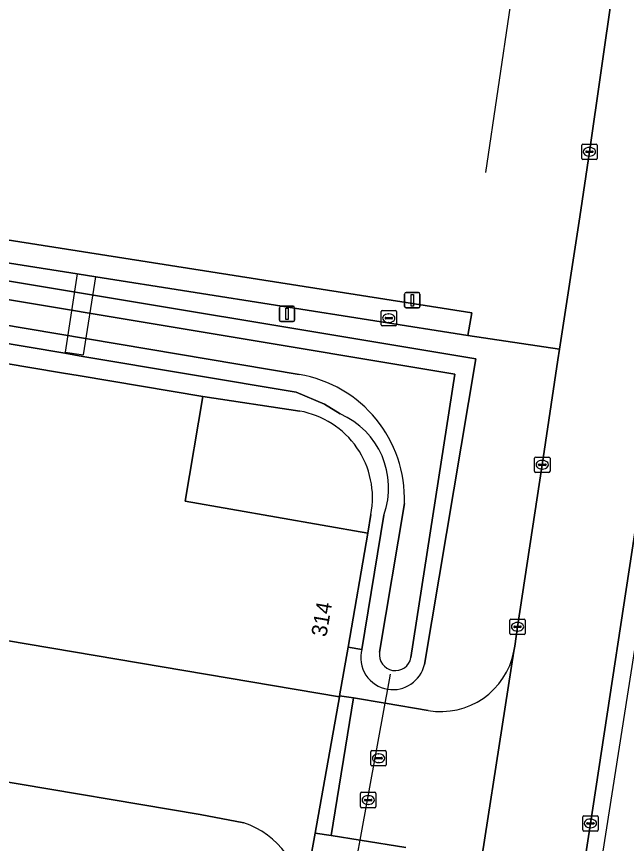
# Model space of a CAD drawing. Extents: x 161090 to 161692, y 379509 to 380907.
# Drawn here: x 161499.4 to 161538.9, y 379916 to 379969.5 of the extents above; entities that cross this region are included whole.
import ezdxf

# ---------------------------------------------------------------- set-up
doc = ezdxf.new("R2010")
doc.units = 0
for name, color, linetype in [('IMGEO_Berm_groen', 7, 'Continuous'), ('IMGEO_Dek', 7, 'Continuous'), ('IMGEO_Duiker', 7, 'Continuous'), ('IMGEO_Erf', 7, 'Continuous'), ('IMGEO_Groenvoorziening', 7, 'Continuous'), ('IMGEO_Hek', 7, 'Continuous'), ('IMGEO_Kolk', 7, 'Continuous'), ('IMGEO_Lichtmast', 7, 'Continuous'), ('IMGEO_Oever', 7, 'Continuous'), ('IMGEO_OVBaan_gesloten', 7, 'Continuous'), ('IMGEO_Pand', 7, 'Continuous'), ('IMGEO_Pand_nummerreeks', 7, 'Continuous'), ('IMGEO_Rijbaan_lokaal_open', 7, 'Continuous'), ('IMGEO_Rioolput', 7, 'Continuous'), ('IMGEO_Voetpad_gesloten', 7, 'Continuous'), ('IMGEO_Voetpad_open', 7, 'Continuous'), ('IMGEO_Waterleidingput', 7, 'Continuous'), ('IMGEO_Waterloop', 7, 'Continuous')]:
    doc.layers.add(name, color=color, linetype=linetype)

msp = doc.modelspace()

# ---------------------------------------------------------------- linework, layer by layer
at = {"layer": 'IMGEO_Berm_groen'}
msp.add_lwpolyline([(161568.964, 380134.54), (161565.202, 380110.378), (161562.114, 380090.616), (161558.714, 380068.427), (161555.445, 380047.213), (161553.622, 380035.058), (161552.155, 380025.015), (161549.143, 380002.747), (161547.501, 379990.953), (161546.186, 379981.488), (161544.637, 379970.686), (161543.025, 379959.699), (161541.406, 379948.743), (161539.958, 379939.476), (161536.563, 379917.273), (161533.152, 379895.072), (161532.543, 379891.174), (161536.797, 379890.693), (161538.081, 379899.575), (161547.32, 379960.011), (161564.94, 380073.828), (161570.943, 380112.605), (161573.298, 380127.137)], dxfattribs=at)
at = {"layer": 'IMGEO_Dek'}
msp.add_lwpolyline([(161503.353, 379952.839), (161502.581, 379947.775), (161503.765, 379947.6), (161504.564, 379952.647)], close=True, dxfattribs=at)
at = {"layer": 'IMGEO_Duiker'}
msp.add_lwpolyline([(161521.213, 379913.764), (161521.359, 379914.557), (161521.659, 379916.19), (161523.289, 379925.051), (161523.456, 379925.959), (161523.636, 379926.94)], dxfattribs=at)
at = {"layer": 'IMGEO_Erf'}
for points in [[(161511.482, 379944.901), (161510.34, 379938.122), (161522.174, 379936.061), (161522.363, 379937.271)], [(161517.757, 379943.954), (161511.482, 379944.901)]]:
    msp.add_lwpolyline(points, dxfattribs=at)
msp.add_arc((161516.777, 379938.35), 5.689, 349.0692, 80.0809, dxfattribs=at)
at = {"layer": 'IMGEO_Groenvoorziening'}
for points in [[(161468.78, 380015.282), (161460.249, 379961.111), (161528.895, 379950.307), (161528.642, 379948.839), (161534.566, 379947.954), (161535.873, 379956.523), (161536.498, 379960.739), (161537.983, 379971.128)], [(161531.614, 379928.422), (161531.665, 379928.747), (161531.848, 379929.997), (161533.448, 379940.484), (161534.462, 379947.272), (161534.566, 379947.954), (161528.642, 379948.839), (161504.564, 379952.647), (161503.353, 379952.839), (161490.618, 379954.853), (161489.414, 379955.043), (161461.018, 379959.534)], [(161463.491, 379958.267), (161529.143, 379947.348), (161525.825, 379927.554)], [(161521.771, 379928.537), (161520.887, 379928.67), (161520.341, 379925.533), (161521.239, 379925.396), (161523.289, 379925.051), (161526.064, 379924.584)], [(161524.623, 379915.703), (161521.659, 379916.19), (161519.795, 379916.496), (161518.754, 379916.647), (161518.179, 379913.425), (161519.482, 379913.207)]]:
    msp.add_lwpolyline(points, dxfattribs=at)
for centre, radius, start, end in [((161523.791, 379928.018), 2.086, 165.5898, 260.7481), ((161526.889, 379929.322), 4.81, 260.1205, 349.2097), ((161523.788, 379928.023), 2.091, 260.8708, 347.0324)]:
    msp.add_arc(centre, radius, start, end, dxfattribs=at)
at = {"layer": 'IMGEO_Hek'}
for points in [[(161554.512, 380126.608), (161529.782, 379959.399)], [(161570.009, 380123.365), (161550.635, 380000), (161531.34, 379877.143), (161526.851, 379847.795)]]:
    msp.add_lwpolyline(points, dxfattribs=at)
at = {"layer": 'IMGEO_Kolk'}
for p, q in [((161535.997, 379960.313), (161535.997, 379961.165)), ((161536.072, 379961.239), (161536.924, 379961.239)), ((161536.485, 379961.019), (161536.51, 379961.019)), ((161536.998, 379961.165), (161536.998, 379960.313)), ((161536.256, 379960.733), (161536.256, 379960.745)), ((161536.694, 379960.696), (161536.296, 379960.696)), ((161536.299, 379960.782), (161536.697, 379960.782)), ((161536.508, 379960.459), (161536.483, 379960.459)), ((161536.74, 379960.745), (161536.74, 379960.733)), ((161536.924, 379960.239), (161536.072, 379960.239)), ((161532.947, 379940.058), (161532.947, 379940.91)), ((161533.022, 379940.984), (161533.874, 379940.984)), ((161533.435, 379940.764), (161533.46, 379940.764)), ((161533.948, 379940.91), (161533.948, 379940.058)), ((161533.206, 379940.478), (161533.206, 379940.49)), ((161533.644, 379940.441), (161533.246, 379940.441)), ((161533.249, 379940.527), (161533.647, 379940.527)), ((161533.458, 379940.204), (161533.433, 379940.204)), ((161533.69, 379940.49), (161533.69, 379940.478)), ((161533.874, 379939.984), (161533.022, 379939.984)), ((161531.347, 379929.571), (161531.347, 379930.423)), ((161531.422, 379930.497), (161532.274, 379930.497)), ((161532.348, 379930.423), (161532.348, 379929.571)), ((161531.606, 379929.991), (161531.606, 379930.003)), ((161532.044, 379929.954), (161531.646, 379929.954)), ((161531.649, 379930.04), (161532.047, 379930.04)), ((161531.835, 379930.277), (161531.86, 379930.277)), ((161532.09, 379930.003), (161532.09, 379929.991)), ((161532.274, 379929.497), (161531.422, 379929.497)), ((161531.858, 379929.717), (161531.833, 379929.717)), ((161536.062, 379916.847), (161536.062, 379917.699)), ((161536.137, 379917.773), (161536.989, 379917.773)), ((161536.55, 379917.553), (161536.575, 379917.553)), ((161537.063, 379917.699), (161537.063, 379916.847)), ((161536.321, 379917.267), (161536.321, 379917.279)), ((161536.759, 379917.23), (161536.361, 379917.23)), ((161536.364, 379917.316), (161536.762, 379917.316)), ((161536.573, 379916.993), (161536.548, 379916.993)), ((161536.805, 379917.279), (161536.805, 379917.267)), ((161536.989, 379916.773), (161536.137, 379916.773))]:
    msp.add_line(p, q, dxfattribs=at)
for points in [[(161535.997, 379960.313), (161535.997, 379961.165)], [(161536.072, 379961.239), (161536.924, 379961.239)], [(161536.998, 379961.165), (161536.998, 379960.313)], [(161536.924, 379960.239), (161536.072, 379960.239)], [(161532.947, 379940.058), (161532.947, 379940.91)], [(161533.022, 379940.984), (161533.874, 379940.984)], [(161533.948, 379940.91), (161533.948, 379940.058)], [(161533.874, 379939.984), (161533.022, 379939.984)], [(161531.347, 379929.571), (161531.347, 379930.423)], [(161531.422, 379930.497), (161532.274, 379930.497)], [(161532.348, 379930.423), (161532.348, 379929.571)], [(161532.274, 379929.497), (161531.422, 379929.497)], [(161536.062, 379916.847), (161536.062, 379917.699)], [(161536.137, 379917.773), (161536.989, 379917.773)], [(161537.063, 379917.699), (161537.063, 379916.847)], [(161536.989, 379916.773), (161536.137, 379916.773)]]:
    msp.add_lwpolyline(points, dxfattribs=at)
for centre, radius, start, end in [((161536.074, 379961.163), 0.0765, 91.552, 178.448), ((161536.074, 379961.163), 0.0765, 91.552, 178.448), ((161536.922, 379961.163), 0.0765, 1.552, 88.448), ((161536.922, 379961.163), 0.0765, 1.552, 88.448), ((161536.296, 379960.742), 0.0403, 85.8775, 175.7526), ((161536.293, 379960.732), 0.0366, 178.938, 274.7102), ((161536.697, 379960.739), 0.043, 264.8664, 352.4533), ((161536.701, 379960.744), 0.0386, 1.7309, 96.639), ((161536.074, 379960.315), 0.0765, 181.552, 268.448), ((161536.074, 379960.315), 0.0765, 181.552, 268.448), ((161536.922, 379960.315), 0.0765, 271.552, 358.448), ((161536.922, 379960.315), 0.0765, 271.552, 358.448), ((161533.024, 379940.908), 0.0765, 91.552, 178.448), ((161533.024, 379940.908), 0.0765, 91.552, 178.448), ((161533.872, 379940.908), 0.0765, 1.552, 88.448), ((161533.872, 379940.908), 0.0765, 1.552, 88.448), ((161533.024, 379940.06), 0.0765, 181.552, 268.448), ((161533.024, 379940.06), 0.0765, 181.552, 268.448), ((161533.246, 379940.487), 0.0403, 85.8775, 175.7526), ((161533.243, 379940.477), 0.0366, 178.938, 274.7102), ((161533.647, 379940.484), 0.043, 264.8664, 352.4533), ((161533.651, 379940.489), 0.0386, 1.7309, 96.639), ((161533.872, 379940.06), 0.0765, 271.552, 358.448), ((161533.872, 379940.06), 0.0765, 271.552, 358.448), ((161531.424, 379930.421), 0.0765, 91.552, 178.448), ((161531.424, 379930.421), 0.0765, 91.552, 178.448), ((161532.272, 379930.421), 0.0765, 1.552, 88.448), ((161532.272, 379930.421), 0.0765, 1.552, 88.448), ((161531.646, 379930), 0.0403, 85.8775, 175.7526), ((161531.643, 379929.99), 0.0366, 178.938, 274.7102), ((161532.047, 379929.997), 0.043, 264.8664, 352.4533), ((161532.051, 379930.002), 0.0386, 1.7309, 96.639), ((161531.424, 379929.573), 0.0765, 181.552, 268.448), ((161531.424, 379929.573), 0.0765, 181.552, 268.448), ((161532.272, 379929.573), 0.0765, 271.552, 358.448), ((161532.272, 379929.573), 0.0765, 271.552, 358.448), ((161536.139, 379917.697), 0.0765, 91.552, 178.448), ((161536.139, 379917.697), 0.0765, 91.552, 178.448), ((161536.987, 379917.697), 0.0765, 1.552, 88.448), ((161536.987, 379917.697), 0.0765, 1.552, 88.448), ((161536.361, 379917.276), 0.0403, 85.8775, 175.7526), ((161536.358, 379917.266), 0.0366, 178.938, 274.7102), ((161536.762, 379917.273), 0.043, 264.8664, 352.4533), ((161536.766, 379917.278), 0.0386, 1.7309, 96.639), ((161536.139, 379916.849), 0.0765, 181.552, 268.448), ((161536.139, 379916.849), 0.0765, 181.552, 268.448), ((161536.987, 379916.849), 0.0765, 271.552, 358.448), ((161536.987, 379916.849), 0.0765, 271.552, 358.448)]:
    msp.add_arc(centre, radius, start, end, dxfattribs=at)
for centre, major_axis, ratio, start_param, end_param in [((161536.484, 379960.739), (-0.387, 0.002), 0.722429, 4.712389, 7.853982), ((161536.509, 379960.739), (-0.39, 0.002), 0.717154, 1.570796, 4.712389), ((161533.434, 379940.484), (-0.387, 0.002), 0.722429, 4.712389, 7.853982), ((161533.459, 379940.484), (-0.39, 0.002), 0.717154, 1.570796, 4.712389), ((161531.834, 379929.997), (-0.387, 0.002), 0.722429, 4.712389, 7.853982), ((161531.859, 379929.997), (-0.39, 0.002), 0.717154, 1.570796, 4.712389), ((161536.549, 379917.273), (-0.387, 0.002), 0.722429, 4.712389, 7.853982), ((161536.574, 379917.273), (-0.39, 0.002), 0.717154, 1.570796, 4.712389)]:
    msp.add_ellipse(centre, major_axis=major_axis, ratio=ratio, start_param=start_param, end_param=end_param, dxfattribs=at)
at = {"layer": 'IMGEO_Lichtmast'}
for p, q in [((161524.543, 379950.731), (161524.543, 379951.531)), ((161524.543, 379951.531), (161524.543, 379950.731)), ((161524.643, 379951.631), (161525.433, 379951.631)), ((161525.433, 379951.631), (161524.643, 379951.631)), ((161525.533, 379951.531), (161525.533, 379950.731)), ((161525.533, 379950.731), (161525.533, 379951.531)), ((161516.541, 379950.748), (161517.331, 379950.748)), ((161517.331, 379950.748), (161516.541, 379950.748)), ((161516.441, 379949.848), (161516.441, 379950.648)), ((161516.441, 379950.648), (161516.441, 379949.848)), ((161517.431, 379950.648), (161517.431, 379949.848)), ((161517.431, 379949.848), (161517.431, 379950.648)), ((161525.433, 379950.631), (161524.643, 379950.631)), ((161524.643, 379950.631), (161525.433, 379950.631)), ((161517.331, 379949.748), (161516.541, 379949.748)), ((161516.541, 379949.748), (161517.331, 379949.748))]:
    msp.add_line(p, q, dxfattribs=at)
for points in [[(161524.963, 379951.506), (161525.113, 379951.506), (161525.113, 379950.756), (161524.963, 379950.756), (161524.963, 379951.506)], [(161516.861, 379950.623), (161517.011, 379950.623), (161517.011, 379949.873), (161516.861, 379949.873), (161516.861, 379950.623)]]:
    msp.add_lwpolyline(points, dxfattribs=at)
for centre, start, end in [((161524.643, 379951.531), 90, 180), ((161524.643, 379951.531), 90, 180), ((161525.433, 379951.531), 0, 90), ((161525.433, 379951.531), 360, 90), ((161516.541, 379950.648), 90, 180), ((161516.541, 379950.648), 90, 180), ((161517.331, 379950.648), 0, 90), ((161517.331, 379950.648), 360, 90), ((161524.643, 379950.731), 180, 270), ((161524.643, 379950.731), 180, 270), ((161525.433, 379950.731), 270, 0), ((161525.433, 379950.731), 270, 0), ((161516.541, 379949.848), 180, 270), ((161516.541, 379949.848), 180, 270), ((161517.331, 379949.848), 270, 0), ((161517.331, 379949.848), 270, 0)]:
    msp.add_arc(centre, 0.1, start, end, dxfattribs=at)
at = {"layer": 'IMGEO_Oever'}
for points in [[(161529.143, 379947.348), (161463.491, 379958.267)], [(161463.297, 379957.103), (161527.787, 379946.344), (161524.955, 379928.002)], [(161517.714, 379946.329), (161463.068, 379955.539)], [(161462.164, 379954.505), (161502.561, 379947.696), (161503.732, 379947.499), (161517.519, 379945.175), (161519.362, 379944.405), (161520.366, 379943.774)], [(161525.825, 379927.554), (161529.143, 379947.348)], [(161522.925, 379928.347), (161524.531, 379937.976)], [(161523.199, 379937.227), (161521.771, 379928.537)]]:
    msp.add_lwpolyline(points, dxfattribs=at)
for centre, radius, start, end in [((161516.378, 379938.281), 8.158, 357.8596, 80.5771), ((161518.312, 379938.999), 5.198, 340.07, 66.7279), ((161523.791, 379928.018), 2.086, 165.5898, 260.7481), ((161523.943, 379928.19), 1.03, 171.2351, 349.4743), ((161523.788, 379928.023), 2.091, 260.8708, 347.0324)]:
    msp.add_arc(centre, radius, start, end, dxfattribs=at)
at = {"layer": 'IMGEO_OVBaan_gesloten'}
for points in [[(161529.449, 379871.979), (161529.771, 379873.901), (161530.767, 379879.919), (161531.052, 379881.64), (161532.543, 379891.174), (161533.152, 379895.072), (161536.563, 379917.273), (161539.958, 379939.476), (161541.406, 379948.743), (161543.025, 379959.699), (161544.637, 379970.686), (161546.186, 379981.488)], [(161537.983, 379971.128), (161536.498, 379960.739), (161535.873, 379956.523), (161534.566, 379947.954), (161534.462, 379947.272), (161533.448, 379940.484), (161531.848, 379929.997), (161531.665, 379928.747), (161531.614, 379928.422), (161528.781, 379910.215), (161528.578, 379908.95), (161527.971, 379905.065), (161526.727, 379897.107), (161524.592, 379883.079), (161523.239, 379874.942)]]:
    msp.add_lwpolyline(points, dxfattribs=at)
at = {"layer": 'IMGEO_Pand'}
for points in [[(161511.482, 379944.901), (161503.555, 379946.236), (161502.356, 379946.438), (161489.675, 379948.574), (161488.466, 379948.778), (161466.406, 379952.494), (161461.941, 379953.246), (161456.443, 379954.173)], [(161451.454, 379952.086), (161451.349, 379951.952), (161450.553, 379950.94), (161449.415, 379949.492), (161448.76, 379948.659), (161443.854, 379942.419), (161443.163, 379941.54), (161439.231, 379936.539), (161438.602, 379935.537), (161438.256, 379934.594), (161438.051, 379933.445), (161438.058, 379932.486), (161438.259, 379931.336), (161438.797, 379929.642), (161448.37, 379928.041), (161449.951, 379937.373), (161520.33, 379925.471), (161520.341, 379925.533), (161520.887, 379928.67), (161522.174, 379936.061), (161510.34, 379938.122), (161511.482, 379944.901)], [(161514.139, 379917.319), (161511.311, 379917.848), (161457.045, 379927.006)]]:
    msp.add_lwpolyline(points, dxfattribs=at)
msp.add_arc((161512.324, 379911.99), 5.629, 1.5838, 71.1895, dxfattribs=at)
at = {"layer": 'IMGEO_Rijbaan_lokaal_open'}
for points in [[(161520.33, 379925.471), (161449.951, 379937.373), (161448.37, 379928.041), (161455.585, 379927.011)], [(161528.781, 379910.215), (161531.614, 379928.422)], [(161457.045, 379927.006), (161511.311, 379917.848), (161514.139, 379917.319)], [(161517.951, 379912.146), (161518.179, 379913.425), (161518.754, 379916.647), (161520.33, 379925.471)], [(161526.064, 379924.584), (161523.289, 379925.051), (161521.239, 379925.396), (161519.795, 379916.496), (161521.659, 379916.19), (161524.623, 379915.703)]]:
    msp.add_lwpolyline(points, dxfattribs=at)
msp.add_lwpolyline([(161521.239, 379925.396), (161520.341, 379925.533), (161520.33, 379925.471), (161518.754, 379916.647), (161519.795, 379916.496)], close=True, dxfattribs=at)
for centre, radius, start, end in [((161526.889, 379929.322), 4.81, 260.1205, 349.2097), ((161512.324, 379911.99), 5.629, 1.5838, 71.1895)]:
    msp.add_arc(centre, radius, start, end, dxfattribs=at)
at = {"layer": 'IMGEO_Rioolput'}
for p, q in [((161522.358, 379921.063), (161522.358, 379921.915)), ((161522.433, 379921.989), (161523.285, 379921.989)), ((161523.359, 379921.915), (161523.359, 379921.063)), ((161522.617, 379921.483), (161522.617, 379921.495)), ((161523.055, 379921.446), (161522.657, 379921.446)), ((161522.66, 379921.532), (161523.058, 379921.532)), ((161522.846, 379921.769), (161522.871, 379921.769)), ((161523.101, 379921.495), (161523.101, 379921.483)), ((161523.285, 379920.989), (161522.433, 379920.989)), ((161522.869, 379921.209), (161522.844, 379921.209)), ((161521.69, 379918.36), (161521.69, 379919.212)), ((161521.765, 379919.286), (161522.617, 379919.286)), ((161522.691, 379919.212), (161522.691, 379918.36)), ((161521.949, 379918.78), (161521.949, 379918.792)), ((161522.387, 379918.743), (161521.989, 379918.743)), ((161521.992, 379918.829), (161522.39, 379918.829)), ((161522.178, 379919.066), (161522.203, 379919.066)), ((161522.433, 379918.792), (161522.433, 379918.78)), ((161522.617, 379918.286), (161521.765, 379918.286)), ((161522.201, 379918.506), (161522.176, 379918.506))]:
    msp.add_line(p, q, dxfattribs=at)
for points in [[(161522.358, 379921.063), (161522.358, 379921.915)], [(161522.433, 379921.989), (161523.285, 379921.989)], [(161523.359, 379921.915), (161523.359, 379921.063)], [(161523.285, 379920.989), (161522.433, 379920.989)], [(161521.69, 379918.36), (161521.69, 379919.212)], [(161521.765, 379919.286), (161522.617, 379919.286)], [(161522.691, 379919.212), (161522.691, 379918.36)], [(161522.617, 379918.286), (161521.765, 379918.286)]]:
    msp.add_lwpolyline(points, dxfattribs=at)
for centre, radius, start, end in [((161522.435, 379921.913), 0.0765, 91.552, 178.448), ((161522.435, 379921.913), 0.0765, 91.552, 178.448), ((161523.283, 379921.913), 0.0765, 1.552, 88.448), ((161523.283, 379921.913), 0.0765, 1.552, 88.448), ((161522.657, 379921.492), 0.0403, 85.8775, 175.7526), ((161522.654, 379921.482), 0.0366, 178.938, 274.7102), ((161523.058, 379921.489), 0.043, 264.8664, 352.4533), ((161523.062, 379921.494), 0.0386, 1.7309, 96.639), ((161522.435, 379921.065), 0.0765, 181.552, 268.448), ((161522.435, 379921.065), 0.0765, 181.552, 268.448), ((161523.283, 379921.065), 0.0765, 271.552, 358.448), ((161523.283, 379921.065), 0.0765, 271.552, 358.448), ((161521.767, 379919.21), 0.0765, 91.552, 178.448), ((161521.767, 379919.21), 0.0765, 91.552, 178.448), ((161522.615, 379919.21), 0.0765, 1.552, 88.448), ((161522.615, 379919.21), 0.0765, 1.552, 88.448), ((161521.989, 379918.789), 0.0403, 85.8775, 175.7526), ((161521.986, 379918.779), 0.0366, 178.938, 274.7102), ((161522.39, 379918.786), 0.043, 264.8664, 352.4533), ((161522.394, 379918.791), 0.0386, 1.7309, 96.639), ((161521.767, 379918.362), 0.0765, 181.552, 268.448), ((161521.767, 379918.362), 0.0765, 181.552, 268.448), ((161522.615, 379918.362), 0.0765, 271.552, 358.448), ((161522.615, 379918.362), 0.0765, 271.552, 358.448)]:
    msp.add_arc(centre, radius, start, end, dxfattribs=at)
for centre, major_axis, ratio, start_param, end_param in [((161522.845, 379921.489), (-0.387, 0.002), 0.722429, 4.712389, 7.853982), ((161522.87, 379921.489), (-0.39, 0.002), 0.717154, 1.570796, 4.712389), ((161522.177, 379918.786), (-0.387, 0.002), 0.722429, 4.712389, 7.853982), ((161522.202, 379918.786), (-0.39, 0.002), 0.717154, 1.570796, 4.712389)]:
    msp.add_ellipse(centre, major_axis=major_axis, ratio=ratio, start_param=start_param, end_param=end_param, dxfattribs=at)
at = {"layer": 'IMGEO_Voetpad_gesloten'}
msp.add_lwpolyline([(161503.353, 379952.839), (161502.581, 379947.775), (161503.765, 379947.6), (161504.564, 379952.647)], close=True, dxfattribs=at)
at = {"layer": 'IMGEO_Voetpad_open'}
for points in [[(161467.557, 380015.417), (161458.422, 379956.887), (161410.982, 379964.353), (161410.798, 379963.231), (161398.503, 379965.191), (161398.507, 379965.05), (161458.269, 379955.609), (161458.131, 379954.643), (161460.184, 379954.317), (161461.018, 379959.534), (161489.414, 379955.043), (161490.618, 379954.853), (161503.353, 379952.839), (161504.564, 379952.647), (161528.642, 379948.839), (161528.895, 379950.307), (161460.249, 379961.111), (161468.78, 380015.282)], [(161503.732, 379947.499), (161502.561, 379947.696), (161462.164, 379954.505), (161461.941, 379953.246), (161466.406, 379952.494), (161488.466, 379948.778), (161488.65, 379950.013), (161489.852, 379949.809), (161489.675, 379948.574), (161502.356, 379946.438), (161503.555, 379946.236), (161511.482, 379944.901), (161517.757, 379943.954)], [(161520.366, 379943.774), (161519.362, 379944.405), (161517.519, 379945.175), (161503.732, 379947.499)], [(161522.363, 379937.271), (161522.174, 379936.061), (161520.887, 379928.67), (161521.771, 379928.537), (161523.199, 379937.227)]]:
    msp.add_lwpolyline(points, dxfattribs=at)
for centre, radius, start, end in [((161516.777, 379938.35), 5.689, 349.0692, 80.0809), ((161518.312, 379938.999), 5.198, 340.07, 66.7279)]:
    msp.add_arc(centre, radius, start, end, dxfattribs=at)
at = {"layer": 'IMGEO_Waterleidingput'}
for p, q in [((161523.018, 379949.543), (161523.018, 379950.395)), ((161523.093, 379950.469), (161523.945, 379950.469)), ((161523.506, 379950.249), (161523.531, 379950.249)), ((161524.019, 379950.395), (161524.019, 379949.543)), ((161523.277, 379949.963), (161523.277, 379949.975)), ((161523.715, 379949.926), (161523.317, 379949.926)), ((161523.32, 379950.012), (161523.718, 379950.012)), ((161523.529, 379949.689), (161523.504, 379949.689)), ((161523.761, 379949.975), (161523.761, 379949.963)), ((161523.945, 379949.469), (161523.093, 379949.469))]:
    msp.add_line(p, q, dxfattribs=at)
for points in [[(161523.018, 379949.543), (161523.018, 379950.395)], [(161523.093, 379950.469), (161523.945, 379950.469)], [(161524.019, 379950.395), (161524.019, 379949.543)], [(161523.945, 379949.469), (161523.093, 379949.469)]]:
    msp.add_lwpolyline(points, dxfattribs=at)
for centre, radius, start, end in [((161523.095, 379950.393), 0.0765, 91.552, 178.448), ((161523.095, 379950.393), 0.0765, 91.552, 178.448), ((161523.943, 379950.393), 0.0765, 1.552, 88.448), ((161523.943, 379950.393), 0.0765, 1.552, 88.448), ((161523.317, 379949.972), 0.0403, 85.8775, 175.7526), ((161523.314, 379949.962), 0.0366, 178.938, 274.7102), ((161523.718, 379949.969), 0.043, 264.8664, 352.4533), ((161523.722, 379949.974), 0.0386, 1.7309, 96.639), ((161523.095, 379949.545), 0.0765, 181.552, 268.448), ((161523.095, 379949.545), 0.0765, 181.552, 268.448), ((161523.943, 379949.545), 0.0765, 271.552, 358.448), ((161523.943, 379949.545), 0.0765, 271.552, 358.448)]:
    msp.add_arc(centre, radius, start, end, dxfattribs=at)
for centre, major_axis, ratio, start_param, end_param in [((161523.505, 379949.969), (-0.387, 0.002), 0.722429, 4.712389, 7.853982), ((161523.53, 379949.969), (-0.39, 0.002), 0.717154, 1.570796, 4.712389)]:
    msp.add_ellipse(centre, major_axis=major_axis, ratio=ratio, start_param=start_param, end_param=end_param, dxfattribs=at)
at = {"layer": 'IMGEO_Waterloop'}
for points in [[(161527.787, 379946.344), (161463.297, 379957.103)], [(161463.068, 379955.539), (161517.714, 379946.329)], [(161524.955, 379928.002), (161527.787, 379946.344)], [(161524.531, 379937.976), (161522.925, 379928.347)]]:
    msp.add_lwpolyline(points, dxfattribs=at)
for centre, radius, start, end in [((161516.378, 379938.281), 8.158, 357.8596, 80.5771), ((161523.943, 379928.19), 1.03, 171.2351, 349.4743)]:
    msp.add_arc(centre, radius, start, end, dxfattribs=at)

# ---------------------------------------------------------------- texts
at = {"layer": 'IMGEO_Pand_nummerreeks'}
msp.add_text('314', height=1, rotation=80.1224, dxfattribs=at).set_placement((161519.475, 379929.301))

doc.saveas('drawing.dxf')
